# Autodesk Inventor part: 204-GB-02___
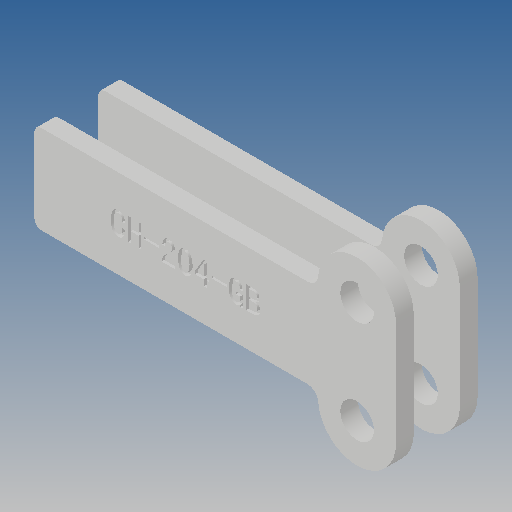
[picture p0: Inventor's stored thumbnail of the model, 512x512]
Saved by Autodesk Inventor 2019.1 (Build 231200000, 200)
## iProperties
Created: 2010-06
Part Number: 204-GB-02___
Material: Ogólny
Document SubType Name: Modeling
Designer: CADENGINEERING4
Density: 1 g/cm^3
Appearance: Domyślna
Author: CADENGINEERING4
Revision Number: ANY
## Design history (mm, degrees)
feature "NONE"
feature "NONE:1"
node "Bryła1"
node "Bryła2"
